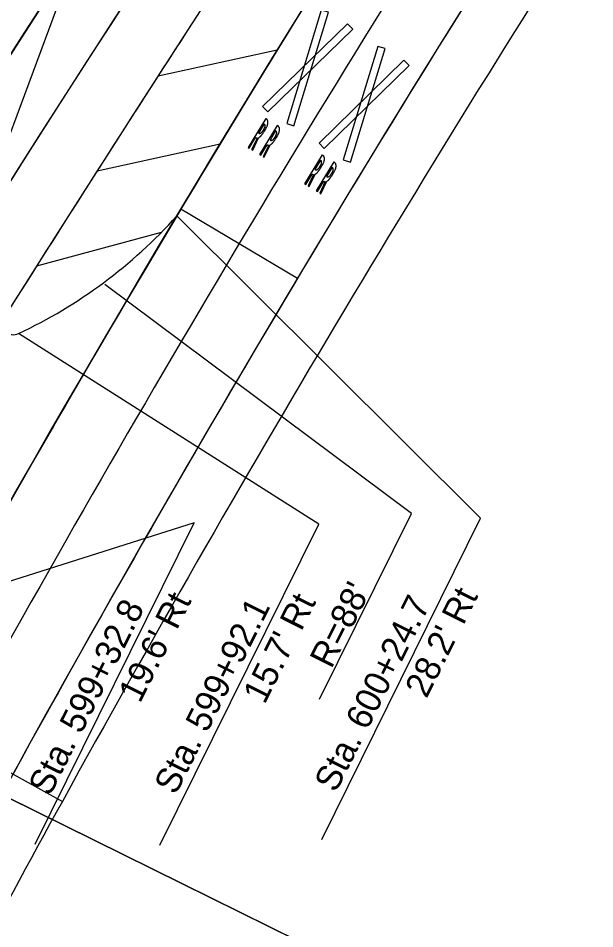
# Model space of a CAD drawing. Extents: x 14097936 to 14128734, y 8632000 to 8683104.
# Drawn here: x 14119093.8 to 14119195.8, y 8668694.3 to 8668855.4 of the extents above; entities that cross this region are included whole.
import ezdxf

# ---------------------------------------------------------------- set-up
doc = ezdxf.new("R2010")
doc.units = 0
for name, color, linetype in [('dsn_stg_shd_prev', 7, 'Continuous'), ('dsnNonPlotable', 7, 'Continuous'), ('dsnPaintPlaceBrokenLaneWhite', 7, 'Continuous'), ('dsnPaintPlaceChannelizingLaneYellow', 7, 'Continuous'), ('dsnPaintPlaceEdgeLineRightWhite', 7, 'Continuous'), ('dsnPaintPlaceStopLineWhite', 7, 'Continuous'), ('dsnShadingPaved', 7, 'Continuous'), ('dsnStgShadingPrevPav', 7, 'Continuous'), ('dsnStgShadingPropPav', 7, 'Continuous'), ('dsnTapeRemoveChannelizingLaneWhite', 7, 'Continuous'), ('Text', 7, 'Continuous'), ('trf_Cells1', 7, 'Continuous')]:
    doc.layers.add(name, color=color, linetype=linetype)

msp = doc.modelspace()

# ---------------------------------------------------------------- linework, layer by layer
at = {"layer": 'dsn_stg_shd_prev'}
msp.add_line((14119071.87, 8668733.2), (14119101.66, 8668716.8), dxfattribs=at)
for centre, radius, start, end in [((14123732.59, 8665873.82), 5512, 146.41866, 157.1633), ((14123732.59, 8665873.82), 5512, 146.50213, 150.36196), ((14121591.75, 8667345.11), 2876.96, 147.23629, 155.33788), ((14121592.11, 8667345.68), 2876.95, 147.23628, 151.16499), ((14121592.11, 8667345.68), 2842.95, 147.24613, 151.16499)]:
    msp.add_arc(centre, radius, start, end, dxfattribs=at)
at = {"layer": 'dsnNonPlotable'}
for points in [[(14118631.64, 8668945.1), (14119326.37, 8670350.23), (14120231.75, 8669902.59), (14119537.02, 8668497.46)], [(14119315.27, 8668607.09), (14120010, 8670012.23), (14119557.31, 8670236.05), (14118862.58, 8668830.91)]]:
    msp.add_lwpolyline(points, close=True, dxfattribs=at)
at = {"layer": 'dsnPaintPlaceBrokenLaneWhite'}
for centre, radius, start, end in [((14121592.11, 8667345.68), 2864.95, 147.15737, 151.16499), ((14123732.96, 8665874.38), 5500, 147.11705, 157.1633)]:
    msp.add_arc(centre, radius, start, end, dxfattribs=at)
at = {"layer": 'dsnPaintPlaceChannelizingLaneYellow'}
for p, q in [((14119118.61, 8668845.22), (14119139.67, 8668849.79)), ((14119107.81, 8668828.39), (14119129.56, 8668833.18)), ((14119119.15, 8668817.49), (14119097.08, 8668811.51))]:
    msp.add_line(p, q, dxfattribs=at)
for centre, radius, start, end in [((14123732.96, 8665874.38), 5488, 146.41498, 147.75486), ((14121592.11, 8667345.68), 2876.95, 147.15737, 149.16283), ((14119056.42, 8668879.21), 88, 295.2058, 318.0673), ((14119093.05, 8668801.39), 2, 147.7549, 295.2058)]:
    msp.add_arc(centre, radius, start, end, dxfattribs=at)
at = {"layer": 'dsnPaintPlaceEdgeLineRightWhite'}
msp.add_arc((14121592.11, 8667345.68), 2852.95, 147.15737, 151.16499, dxfattribs=at)
at = {"layer": 'dsnPaintPlaceStopLineWhite'}
msp.add_line((14119143.22, 8668809.32), (14119122.62, 8668821.63), dxfattribs=at)
at = {"layer": 'dsnShadingPaved'}
for centre, radius, start, end in [((14123732.96, 8665874.38), 5500, 145.2497, 157.1633), ((14123732.96, 8665874.38), 5488, 145.2497, 157.1633), ((14123732.96, 8665874.38), 5500, 146.42378, 157.1633), ((14121592.11, 8667345.68), 2876.95, 147.15737, 157.1633), ((14121592.11, 8667345.68), 2852.95, 147.15737, 157.1633), ((14123655.03, 8665915.77), 5424.12, 146.80648, 157.24675), ((14123056.19, 8666307.54), 4708.51, 146.80648, 147.95139), ((14121592.11, 8667345.68), 2876.95, 149.16283, 157.1633), ((14119056.42, 8668879.21), 88, 295.2058, 318.0673), ((14119093.05, 8668801.39), 2, 147.7549, 295.2058)]:
    msp.add_arc(centre, radius, start, end, dxfattribs=at)
at = {"layer": 'dsnStgShadingPrevPav'}
for centre, radius, start, end in [((14123732.96, 8665874.38), 5512, 146.41866, 157.1633), ((14121592.12, 8667345.67), 2876.96, 147.23629, 155.33788)]:
    msp.add_arc(centre, radius, start, end, dxfattribs=at)
at = {"layer": 'dsnStgShadingPropPav'}
msp.add_line((14119071.87, 8668733.2), (14119101.66, 8668716.8), dxfattribs=at)
msp.add_line((14119071.87, 8668733.2), (14119101.66, 8668716.8), dxfattribs=at)
for centre, radius, start, end in [((14123732.59, 8665873.82), 5512, 146.50213, 150.36196), ((14121592.11, 8667345.68), 2876.95, 147.23628, 151.16499), ((14121592.11, 8667345.68), 2842.95, 147.24613, 151.16499), ((14121592.11, 8667345.68), 2842.95, 151.16499, 152.63404)]:
    msp.add_arc(centre, radius, start, end, dxfattribs=at)
at = {"layer": 'dsnTapeRemoveChannelizingLaneWhite'}
msp.add_line((14118983.04, 8668540.5), (14119108.11, 8668877.26), dxfattribs=at)
at = {"layer": 'Text'}
for points in [[(14119147.54, 8668710.08), (14119175.64, 8668766.92), (14119121.89, 8668820.4)], [(14119147.13, 8668734.87), (14119163.39, 8668767.76), (14119109.18, 8668808.26)], [(14119118.88, 8668709.03), (14119146.99, 8668765.87), (14119093.9, 8668799.58)], [(14119096.84, 8668709.23), (14119124.94, 8668766.07), (14119066.02, 8668747.42)]]:
    msp.add_lwpolyline(points, dxfattribs=at)
at = {"layer": 'trf_Cells1'}
for p, q in [((14119137.33, 8668836.72), (14119136.33, 8668835.08)), ((14119137.32, 8668835.32), (14119137.57, 8668835.73)), ((14119139.38, 8668835.47), (14119138.38, 8668833.83)), ((14119139.37, 8668834.07), (14119139.62, 8668834.48)), ((14119147.33, 8668830.27), (14119146.33, 8668828.63)), ((14119147.32, 8668828.87), (14119147.57, 8668829.28)), ((14119149.38, 8668829.02), (14119148.38, 8668827.38)), ((14119149.37, 8668827.62), (14119149.62, 8668828.03))]:
    msp.add_line(p, q, dxfattribs=at)
for points in [[(14119142.61, 8668836.38), (14119148.73, 8668856.46), (14119147.45, 8668856.85), (14119141.34, 8668836.77)], [(14119137.06, 8668839.76), (14119152.07, 8668854.42), (14119153.01, 8668853.47), (14119137.99, 8668838.81)], [(14119152.61, 8668829.93), (14119158.73, 8668850.01), (14119157.45, 8668850.4), (14119151.34, 8668830.32)], [(14119147.06, 8668833.31), (14119162.08, 8668847.97), (14119163.01, 8668847.02), (14119147.99, 8668832.35)]]:
    msp.add_lwpolyline(points, close=True, dxfattribs=at)
for points in [[(14119137.62, 8668837.66), (14119134.5, 8668832.54), (14119134.71, 8668832.41), (14119135.83, 8668834.26)], [(14119139.67, 8668836.42), (14119136.55, 8668831.29), (14119136.76, 8668831.17), (14119137.88, 8668833.01)], [(14119136.1, 8668834.19), (14119135.12, 8668832.16), (14119135.32, 8668832.04), (14119136.36, 8668834.24)], [(14119138.15, 8668832.94), (14119137.17, 8668830.92), (14119137.37, 8668830.79), (14119138.41, 8668832.99)], [(14119147.62, 8668831.21), (14119144.51, 8668826.08), (14119144.71, 8668825.96), (14119145.83, 8668827.81)], [(14119149.67, 8668829.96), (14119146.56, 8668824.84), (14119146.76, 8668824.71), (14119147.88, 8668826.56)], [(14119146.1, 8668827.74), (14119145.12, 8668825.71), (14119145.33, 8668825.59), (14119146.36, 8668827.79)], [(14119148.15, 8668826.49), (14119147.17, 8668824.46), (14119147.38, 8668824.34), (14119148.41, 8668826.54)]]:
    msp.add_lwpolyline(points, dxfattribs=at)
for points in [[(14119137.57, 8668835.73), (14119137.77, 8668836.08), (14119137.85, 8668836.24), (14119137.9, 8668836.39), (14119137.95, 8668836.52), (14119137.98, 8668836.64), (14119138.01, 8668836.81), (14119138.02, 8668836.92), (14119138.02, 8668837.03), (14119138.01, 8668837.11), (14119137.99, 8668837.22), (14119137.97, 8668837.28), (14119137.94, 8668837.36), (14119137.9, 8668837.41), (14119137.85, 8668837.48), (14119137.81, 8668837.52), (14119137.75, 8668837.57), (14119137.62, 8668837.66)], [(14119136.33, 8668835.08), (14119136.41, 8668835.05), (14119136.48, 8668835.03), (14119136.54, 8668835.02), (14119136.61, 8668835.03), (14119136.69, 8668835.05), (14119136.75, 8668835.08), (14119136.8, 8668835.12), (14119136.87, 8668835.17), (14119136.93, 8668835.22), (14119137.03, 8668835.34), (14119137.1, 8668835.44), (14119137.17, 8668835.54), (14119137.24, 8668835.65)], [(14119136.36, 8668834.24), (14119136.4, 8668834.26), (14119136.49, 8668834.31), (14119136.6, 8668834.4), (14119136.66, 8668834.45), (14119136.76, 8668834.55), (14119136.84, 8668834.64), (14119136.89, 8668834.71), (14119136.98, 8668834.82), (14119137.06, 8668834.93), (14119137.12, 8668835.02), (14119137.19, 8668835.13), (14119137.32, 8668835.32)], [(14119137.24, 8668835.65), (14119137.31, 8668835.76), (14119137.37, 8668835.87), (14119137.42, 8668835.97), (14119137.47, 8668836.12), (14119137.49, 8668836.19), (14119137.51, 8668836.28), (14119137.52, 8668836.35), (14119137.52, 8668836.42), (14119137.5, 8668836.49), (14119137.47, 8668836.56), (14119137.44, 8668836.61), (14119137.39, 8668836.66), (14119137.33, 8668836.72)], [(14119139.29, 8668834.4), (14119139.36, 8668834.52), (14119139.42, 8668834.62), (14119139.47, 8668834.73), (14119139.52, 8668834.87), (14119139.54, 8668834.95), (14119139.56, 8668835.04), (14119139.57, 8668835.1), (14119139.57, 8668835.17), (14119139.55, 8668835.24), (14119139.52, 8668835.31), (14119139.49, 8668835.36), (14119139.44, 8668835.42), (14119139.38, 8668835.47)], [(14119139.62, 8668834.48), (14119139.82, 8668834.83), (14119139.9, 8668835), (14119139.95, 8668835.14), (14119140, 8668835.28), (14119140.03, 8668835.4), (14119140.06, 8668835.57), (14119140.07, 8668835.68), (14119140.07, 8668835.78), (14119140.06, 8668835.86), (14119140.04, 8668835.97), (14119140.02, 8668836.04), (14119139.99, 8668836.11), (14119139.95, 8668836.17), (14119139.9, 8668836.23), (14119139.86, 8668836.27), (14119139.8, 8668836.33), (14119139.67, 8668836.42)], [(14119135.83, 8668834.26), (14119135.92, 8668834.22), (14119136.03, 8668834.2), (14119136.1, 8668834.19)], [(14119138.38, 8668833.83), (14119138.46, 8668833.8), (14119138.53, 8668833.78), (14119138.59, 8668833.78), (14119138.66, 8668833.78), (14119138.74, 8668833.8), (14119138.8, 8668833.83), (14119138.85, 8668833.87), (14119138.92, 8668833.93), (14119138.98, 8668833.98), (14119139.08, 8668834.09), (14119139.15, 8668834.19), (14119139.22, 8668834.29), (14119139.29, 8668834.4)], [(14119138.41, 8668832.99), (14119138.45, 8668833.01), (14119138.54, 8668833.07), (14119138.65, 8668833.15), (14119138.71, 8668833.2), (14119138.81, 8668833.3), (14119138.89, 8668833.39), (14119138.94, 8668833.46), (14119139.03, 8668833.57), (14119139.11, 8668833.69), (14119139.17, 8668833.77), (14119139.24, 8668833.88), (14119139.37, 8668834.07)], [(14119137.88, 8668833.01), (14119137.97, 8668832.97), (14119138.08, 8668832.95), (14119138.15, 8668832.94)], [(14119147.57, 8668829.28), (14119147.77, 8668829.62), (14119147.85, 8668829.79), (14119147.91, 8668829.94), (14119147.95, 8668830.07), (14119147.98, 8668830.19), (14119148.01, 8668830.36), (14119148.02, 8668830.47), (14119148.02, 8668830.57), (14119148.01, 8668830.66), (14119147.99, 8668830.77), (14119147.97, 8668830.83), (14119147.94, 8668830.9), (14119147.9, 8668830.96), (14119147.86, 8668831.02), (14119147.81, 8668831.07), (14119147.75, 8668831.12), (14119147.62, 8668831.21)], [(14119146.33, 8668828.63), (14119146.41, 8668828.6), (14119146.48, 8668828.58), (14119146.54, 8668828.57), (14119146.61, 8668828.58), (14119146.69, 8668828.6), (14119146.75, 8668828.63), (14119146.8, 8668828.66), (14119146.87, 8668828.72), (14119146.93, 8668828.77), (14119147.03, 8668828.89), (14119147.11, 8668828.98), (14119147.17, 8668829.08), (14119147.24, 8668829.2)], [(14119146.36, 8668827.79), (14119146.4, 8668827.81), (14119146.49, 8668827.86), (14119146.6, 8668827.94), (14119146.66, 8668828), (14119146.76, 8668828.09), (14119146.84, 8668828.19), (14119146.89, 8668828.26), (14119146.98, 8668828.36), (14119147.06, 8668828.48), (14119147.12, 8668828.56), (14119147.19, 8668828.67), (14119147.32, 8668828.87)], [(14119147.24, 8668829.2), (14119147.31, 8668829.31), (14119147.37, 8668829.41), (14119147.42, 8668829.52), (14119147.48, 8668829.66), (14119147.49, 8668829.74), (14119147.51, 8668829.83), (14119147.52, 8668829.9), (14119147.52, 8668829.96), (14119147.5, 8668830.04), (14119147.48, 8668830.1), (14119147.44, 8668830.16), (14119147.39, 8668830.21), (14119147.33, 8668830.27)], [(14119149.29, 8668827.95), (14119149.36, 8668828.06), (14119149.42, 8668828.17), (14119149.47, 8668828.27), (14119149.53, 8668828.42), (14119149.55, 8668828.49), (14119149.56, 8668828.58), (14119149.57, 8668828.65), (14119149.57, 8668828.72), (14119149.55, 8668828.79), (14119149.53, 8668828.86), (14119149.49, 8668828.91), (14119149.44, 8668828.96), (14119149.38, 8668829.02)], [(14119149.62, 8668828.03), (14119149.82, 8668828.38), (14119149.9, 8668828.54), (14119149.96, 8668828.69), (14119150, 8668828.82), (14119150.03, 8668828.94), (14119150.06, 8668829.11), (14119150.07, 8668829.22), (14119150.07, 8668829.33), (14119150.06, 8668829.41), (14119150.04, 8668829.52), (14119150.02, 8668829.58), (14119149.99, 8668829.66), (14119149.95, 8668829.71), (14119149.91, 8668829.78), (14119149.86, 8668829.82), (14119149.8, 8668829.87), (14119149.67, 8668829.96)], [(14119145.83, 8668827.81), (14119145.92, 8668827.77), (14119146.03, 8668827.74), (14119146.1, 8668827.74)], [(14119148.38, 8668827.38), (14119148.46, 8668827.35), (14119148.53, 8668827.33), (14119148.59, 8668827.32), (14119148.66, 8668827.33), (14119148.74, 8668827.35), (14119148.8, 8668827.38), (14119148.85, 8668827.42), (14119148.93, 8668827.47), (14119148.98, 8668827.52), (14119149.08, 8668827.64), (14119149.16, 8668827.74), (14119149.22, 8668827.84), (14119149.29, 8668827.95)], [(14119148.41, 8668826.54), (14119148.45, 8668826.56), (14119148.54, 8668826.61), (14119148.65, 8668826.7), (14119148.71, 8668826.75), (14119148.81, 8668826.85), (14119148.89, 8668826.94), (14119148.94, 8668827.01), (14119149.03, 8668827.12), (14119149.11, 8668827.23), (14119149.17, 8668827.32), (14119149.24, 8668827.43), (14119149.37, 8668827.62)], [(14119147.88, 8668826.56), (14119147.97, 8668826.52), (14119148.08, 8668826.5), (14119148.15, 8668826.49)]]:
    msp.add_spline(points, degree=3, dxfattribs=at)

# ---------------------------------------------------------------- texts
at = {"layer": 'Text'}
for s, height, p in [("R=88'", 4.484, (14119149.24, 8668740.12)), ("19.6' Rt", 4.484, (14119115.37, 8668734.03)), ("15.7' Rt", 4.484, (14119137.41, 8668733.83)), ('Sta. 600+24.7', 4.4845, (14119150.03, 8668718.2)), ("28.2' Rt", 4.484, (14119166.07, 8668734.88)), ('Sta. 599+32.8', 4.4845, (14119099.43, 8668717.54)), ('Sta. 599+92.1', 4.4845, (14119121.7, 8668717.78))]:
    msp.add_text(s, height=height, rotation=63.3424, dxfattribs=at).set_placement(p)

doc.saveas('drawing.dxf')
